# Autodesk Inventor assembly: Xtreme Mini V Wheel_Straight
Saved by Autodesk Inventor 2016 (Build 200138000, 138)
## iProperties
Created: 2015-11
Part Number: Xtreme Mini V Wheel_Straight
Document SubType Name: Assembly
Designer: John
Author: John
Revision Number: ANY
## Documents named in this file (6)
- D:\3D Printer Designs\John Ledden Designs\DLP Printer\STEP Parts Library 1.1\Assemblies\C-Beam Linear Actuator\Xtreme Mini V Wheel_Straight.iam
- D:\3D Printer Designs\John Ledden Designs\DLP Printer\STEP Parts Library 1.1\Assemblies\C-Beam Linear Actuator\Xtreme Mini V Wheel.ipt
- D:\3D Printer Designs\John Ledden Designs\DLP Printer\STEP Parts Library 1.1\Assemblies\C-Beam Linear Actuator\Ball Bearing 5 x 10 x 4.2.ipt
- D:\3D Printer Designs\John Ledden Designs\DLP Printer\STEP Parts Library 1.1\Assemblies\C-Beam Linear Actuator\Precision Shim 8 x 5 x 1.ipt
- D:\3D Printer Designs\John Ledden Designs\DLP Printer\STEP Parts Library 1.1\Assemblies\C-Beam Linear Actuator\Nylon Insert Lock Nut M5.ipt
- D:\3D Printer Designs\John Ledden Designs\DLP Printer\STEP Parts Library 1.1\Assemblies\C-Beam Linear Actuator\Aluminum Spacer 6mm.ipt
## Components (7 placed, 7 different names)
1. Xtreme Mini V Wheel_48
2. Ball Bearing 5 x 10 x 4.2_49
3. Ball Bearing 5 x 10 x 4.2_50
4. Precision Shim 8 x 5 x 1_51
5. Precision Shim 8 x 5 x 1_52
6. Nylon Insert Lock Nut M5_53
7. Aluminum Spacer 6mm_54
